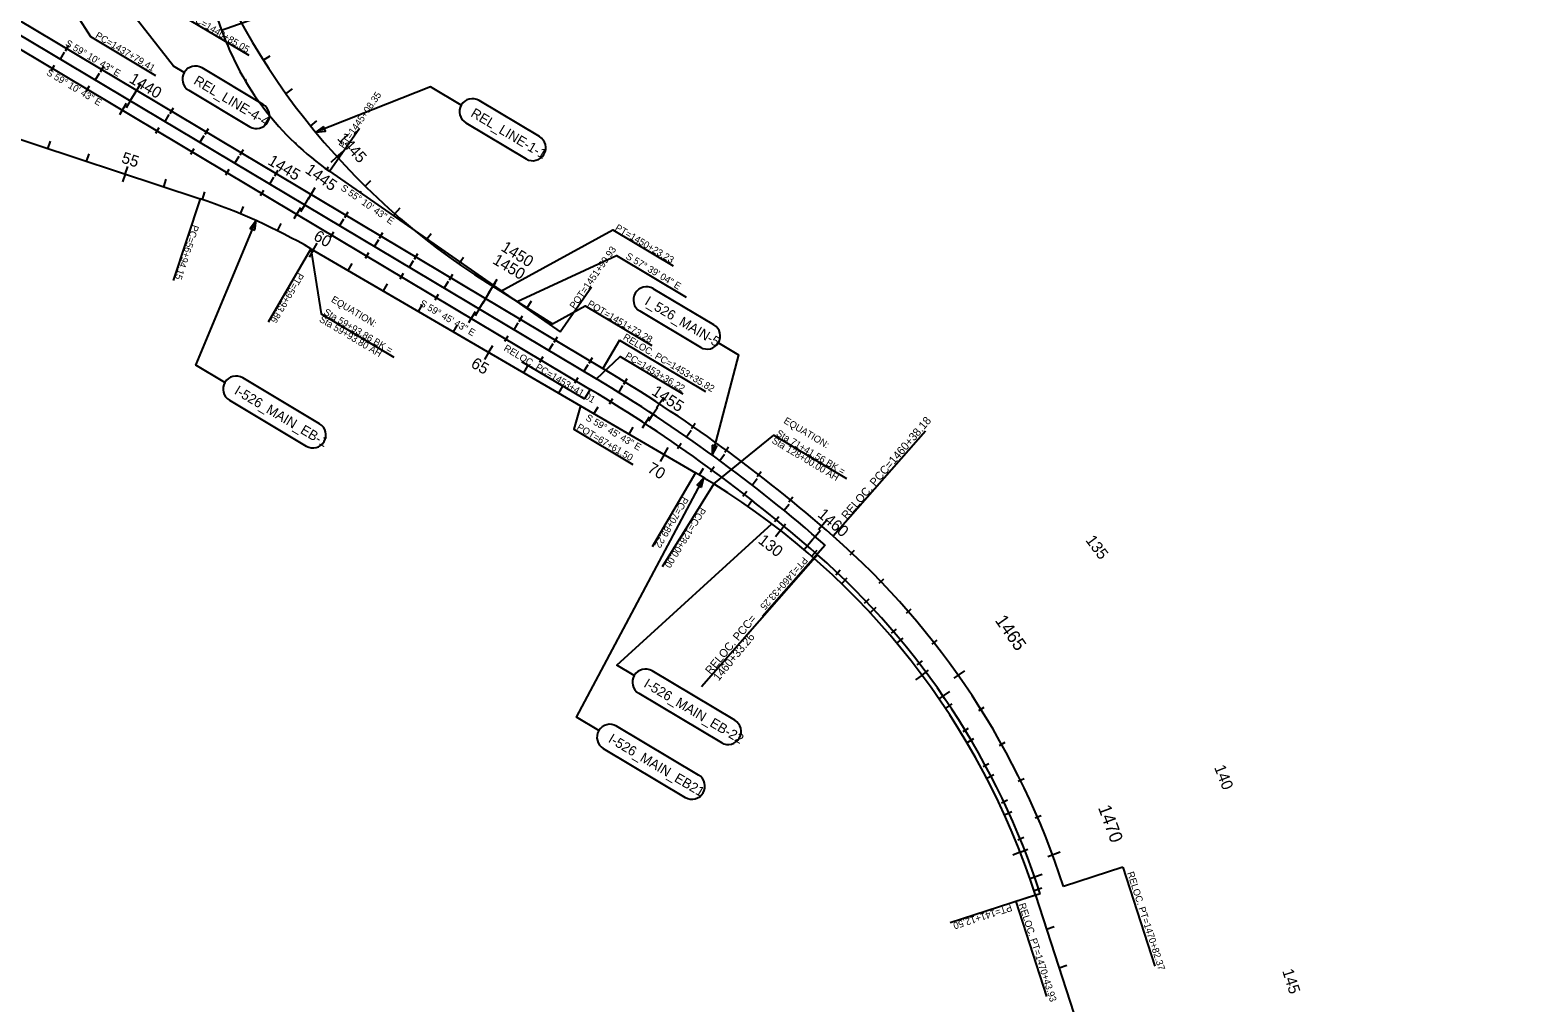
# Model space of a CAD drawing. Extents: x 2339300 to 2355400, y 360879 to 381052.
# Drawn here: x 2349719 to 2353429, y 365467 to 367862 of the extents above; entities that cross this region are included whole.
import ezdxf

# ---------------------------------------------------------------- set-up
doc = ezdxf.new("R2010")
doc.units = 0
for name, color, linetype in [('RD_HC_Cl', 7, 'Continuous'), ('RD_HC_CL_Rel', 7, 'Continuous'), ('RD_HC_Data', 7, 'Continuous'), ('RD_HC_Data_Rel', 7, 'Continuous'), ('RD_HC_Data_Tic', 7, 'Continuous'), ('RD_HC_Data_Tic_Rel', 7, 'Continuous'), ('RD_HC_TX_Rel_Sta50', 7, 'Continuous'), ('RD_HC_TX_Sta50', 7, 'Continuous')]:
    doc.layers.add(name, color=color, linetype=linetype)

msp = doc.modelspace()

# ---------------------------------------------------------------- linework, layer by layer
at = {"layer": 'RD_HC_Cl'}
for p, q in [((2346281.6, 369885.4), (2351112.4, 367003.2)), ((2350024.7, 368324.9), (2350189.7, 367861.9)), ((2348946.1, 367839.1), (2350136.8, 367446.4)), ((2350455.3, 367514.3), (2351023.1, 367119.4)), ((2350409.6, 367323.6), (2351072.9, 366937)), ((2351072.9, 366937), (2351356, 366771.9)), ((2352192.8, 365732.2), (2353428.7, 361905))]:
    msp.add_line(p, q, dxfattribs=at)
for centre, radius, start, end in [((2350864.3, 368102.3), 716.2, 199.6124, 235.1785), ((2349688.3, 366086.1), 1432.4, 59.7618, 71.7499), ((2349155.3, 363723), 3819.7, 48.7231, 59.1785), ((2350415.3, 365158.2), 1867.9, 58.1564, 59.7618), ((2350415.3, 365158.2), 1867.9, 17.896, 58.1564)]:
    msp.add_arc(centre, radius, start, end, dxfattribs=at)
at = {"layer": 'RD_HC_CL_Rel'}
for p, q in [((2348614.8, 368528.3), (2351127.8, 367029)), ((2348584, 368476.8), (2351097, 366977.5))]:
    msp.add_line(p, q, dxfattribs=at)
for centre, radius, start, end in [((2349155.3, 363723), 3849.7, 48.7252, 59.1785), ((2349155.3, 363723), 3789.7, 48.7126, 59.1785), ((2350414.7, 365157.8), 1940.6, 17.896, 48.7252), ((2350416, 365158.6), 1879.1, 17.896, 48.7126)]:
    msp.add_arc(centre, radius, start, end, dxfattribs=at)
at = {"layer": 'RD_HC_Data'}
for p, q in [((2350189.7, 367861.9), (2350312.2, 367905.5)), ((2350292, 367679.1), (2350141.6, 367768.8)), ((2350108.8, 367713.8), (2350259.2, 367624.1)), ((2350972, 367599.9), (2350823.5, 367688.5)), ((2350455.3, 367514.3), (2350529.3, 367620.6)), ((2350790.7, 367633.6), (2350939.2, 367544.9)), ((2350136.8, 367446.4), (2350070.7, 367245.7)), ((2350409.6, 367323.6), (2350304.2, 367142.7)), ((2351023.1, 367119.4), (2351099.9, 367229.8)), ((2351401.2, 367136.2), (2351251.5, 367225.4)), ((2351218.7, 367170.5), (2351368.4, 367081.2)), ((2350431, 366892.8), (2350241.8, 367005.7)), ((2350209, 366950.8), (2350398.2, 366837.9)), ((2351356, 366771.9), (2351249.7, 366589.5)), ((2351400.8, 366744.9), (2351273.9, 366540.5)), ((2351675.2, 366593.6), (2351521.1, 366418.1)), ((2351452.7, 366162.9), (2351249.1, 366284.3)), ((2351216.3, 366229.4), (2351419.9, 366107.9)), ((2351363.7, 366028), (2351161.8, 366148.5)), ((2351129, 366093.5), (2351330.9, 365973.1)), ((2352192.8, 365732.2), (2351982.4, 365664.2))]:
    msp.add_line(p, q, dxfattribs=at)
for points in [[(2350097.8, 367757.7), (2350071.6, 367773.3), (2349979.6, 367890.6)], [(2350779.6, 367677.5), (2350704, 367722.6), (2350421.3, 367610.5)], [(2350197.9, 366994.7), (2350126.7, 367037.1), (2350274.7, 367392.9)], [(2350409.6, 367323.6), (2350434.6, 367163.7), (2350613.8, 367056.8)], [(2351412.3, 367092.3), (2351461.9, 367062.7), (2351396.9, 366815.8)], [(2351112.4, 367003.2), (2351170.7, 367058.3), (2351324.7, 366966.4)], [(2351072.9, 366937), (2351056.7, 366879.3), (2351201.8, 366792.8)], [(2351400.8, 366744.9), (2351548.5, 366864.6), (2351727.1, 366758.1)], [(2351118, 366137.4), (2351062.8, 366170.3), (2351376.1, 366760)], [(2351205.2, 366273.3), (2351162.1, 366299), (2351544.1, 366646.6)]]:
    msp.add_lwpolyline(points, dxfattribs=at)
for points in [[(2350440.5, 367624.8), (2350421.3, 367610.5), (2350445.1, 367613.2)], [(2350271.5, 367369.1), (2350274.7, 367392.9), (2350260, 367373.9)], [(2351396.8, 366839.8), (2351396.9, 366815.8), (2351408.8, 366836.6)], [(2351370.7, 366736.6), (2351376.1, 366760), (2351359.7, 366742.5)]]:
    msp.add_lwpolyline(points, close=True, dxfattribs=at)
for centre, start, end in [((2350125.2, 367741.3), 59.1784, 239.1784), ((2350275.6, 367651.6), 239.1784, 59.1784), ((2350807.1, 367661.1), 59.1784, 239.1784), ((2350955.6, 367572.4), 239.1784, 59.1784), ((2351235.1, 367198), 59.1784, 239.1784), ((2351384.8, 367108.7), 239.1784, 59.1784), ((2350225.4, 366978.3), 59.1784, 239.1784), ((2350414.6, 366865.3), 239.1784, 59.1784), ((2351232.7, 366256.9), 59.1784, 239.1784), ((2351145.4, 366121), 59.1784, 239.1784), ((2351436.3, 366135.4), 239.1784, 59.1784), ((2351347.3, 366000.6), 239.1784, 59.1784)]:
    msp.add_arc(centre, 32, start, end, dxfattribs=at)
at = {"layer": 'RD_HC_Data_Rel'}
for p, q in [((2350877, 367219.4), (2351003.7, 367139.1)), ((2351169.3, 367098.6), (2351127.8, 367029)), ((2351169.3, 367098.6), (2351380.9, 366972.3)), ((2350927.9, 367046.4), (2351083, 366953.9)), ((2351097, 366977.5), (2351083, 366953.9)), ((2351921.5, 366874.4), (2351694.9, 366616.2)), ((2351655.9, 366570.6), (2351370.5, 366245.6)), ((2352407.6, 365801.3), (2352261.4, 365754.1)), ((2352407.6, 365801.3), (2352486.2, 365557.7)), ((2352204.2, 365736.1), (2352144.3, 365716.7)), ((2352144.3, 365716.7), (2352219.9, 365482.6))]:
    msp.add_line(p, q, dxfattribs=at)
for points in [[(2350072.1, 368005), (2350092.2, 367898.3), (2350256.6, 367800.3)], [(2349833.3, 367899.1), (2349867.6, 367845.8), (2350027.4, 367750.5)], [(2350877, 367219.4), (2351152.7, 367370.2), (2351301.1, 367281.6)], [(2350917.1, 367193.9), (2351161.6, 367307), (2351332.7, 367204.9)], [(2351003.7, 367139.1), (2351084.7, 367182.8), (2351248.1, 367085.3)]]:
    msp.add_lwpolyline(points, dxfattribs=at)
msp.add_arc((2351779.9, 368732.5), 1762, 199.588, 239.1733, dxfattribs=at)
at = {"layer": 'RD_HC_Data_Tic'}
for p, q in [((2349793.1, 367790.3), (2349803.4, 367807.5)), ((2350202.7, 367828), (2350206.4, 367829.6)), ((2349879, 367739.1), (2349889.3, 367756.3)), ((2350247.3, 367738.6), (2350250.7, 367740.7)), ((2349964.9, 367687.9), (2349975.1, 367705)), ((2349964.9, 367687.9), (2349954.6, 367670.7)), ((2350303.9, 367656.3), (2350307, 367658.8)), ((2350050.8, 367636.6), (2350061, 367653.8)), ((2349762.5, 367569.8), (2349768.8, 367588.8)), ((2350136.6, 367585.4), (2350146.9, 367602.6)), ((2350371.4, 367582.6), (2350374.2, 367585.5)), ((2349857.5, 367538.5), (2349863.7, 367557.5)), ((2350222.5, 367534.1), (2350232.8, 367551.3)), ((2349952.5, 367507.2), (2349958.7, 367526.2)), ((2350448.5, 367519.1), (2350453.2, 367525.6)), ((2349952.5, 367507.2), (2349946.2, 367488.2)), ((2350047.4, 367475.9), (2350053.7, 367494.9)), ((2350308.4, 367482.9), (2350318.6, 367500.1)), ((2350142.4, 367444.6), (2350148.7, 367463.5)), ((2350394.3, 367431.7), (2350404.5, 367448.8)), ((2350530.6, 367462), (2350532.9, 367465.2)), ((2350236, 367409.6), (2350243.7, 367428.1)), ((2350394.3, 367431.7), (2350384, 367414.5)), ((2350612.7, 367404.9), (2350615, 367408.1)), ((2350327, 367368.1), (2350336, 367386)), ((2350480.2, 367380.4), (2350490.4, 367397.6)), ((2350415, 367320.4), (2350425, 367337.7)), ((2350566, 367329.2), (2350576.3, 367346.4)), ((2350694.8, 367347.8), (2350697.1, 367351)), ((2350415, 367320.4), (2350404.9, 367303.2)), ((2350501.4, 367270.1), (2350511.4, 367287.4)), ((2350651.9, 367278), (2350662.2, 367295.1)), ((2350776.9, 367290.7), (2350779.1, 367293.9)), ((2350587.8, 367219.7), (2350597.8, 367237)), ((2350737.8, 367226.7), (2350748, 367243.9)), ((2350859, 367233.6), (2350863.5, 367240.1)), ((2350674.2, 367169.4), (2350684.2, 367186.6)), ((2350823.7, 367175.5), (2350813.4, 367158.3)), ((2350823.7, 367175.5), (2350833.9, 367192.7)), ((2350941, 367176.5), (2350943.3, 367179.7)), ((2350909.5, 367124.3), (2350919.8, 367141.4)), ((2350760.5, 367119), (2350770.6, 367136.3)), ((2350846.9, 367068.6), (2350836.9, 367051.4)), ((2350846.9, 367068.6), (2350857, 367085.9)), ((2350995.4, 367073), (2351005.7, 367090.2)), ((2350933.3, 367018.3), (2350943.4, 367035.6)), ((2351081.3, 367021.8), (2351091.5, 367039)), ((2351019.7, 366967.9), (2351029.8, 366985.2)), ((2351166.9, 366970.1), (2351177.4, 366987.1)), ((2351106.1, 366917.6), (2351116.2, 366934.8)), ((2351251.2, 366916.3), (2351240.2, 366899.6)), ((2351251.2, 366916.3), (2351262.2, 366933)), ((2351192.5, 366867.2), (2351202.6, 366884.5)), ((2351334.1, 366860.4), (2351345.5, 366876.8)), ((2351278.9, 366816.8), (2351268.8, 366799.6)), ((2351278.9, 366816.8), (2351289, 366834.1)), ((2351415.5, 366802.3), (2351427.3, 366818.4)), ((2351365.3, 366766.5), (2351375.5, 366783.7)), ((2351495.3, 366742), (2351507.5, 366757.8)), ((2351484.3, 366689.9), (2351495.8, 366706.3)), ((2351573.5, 366679.7), (2351586.2, 366695.2)), ((2351564.8, 366630.5), (2351552.5, 366614.8)), ((2351564.8, 366630.5), (2351577.1, 366646.3)), ((2351650.1, 366615.4), (2351663.2, 366630.6)), ((2351650.1, 366615.4), (2351637, 366600.3)), ((2351641.9, 366566.9), (2351655, 366582)), ((2351715.5, 366499.2), (2351729.4, 366513.6)), ((2351785.4, 366427.8), (2351800.1, 366441.3)), ((2351851.4, 366352.6), (2351866.8, 366365.4)), ((2351913.3, 366274.1), (2351929.3, 366286)), ((2351913.3, 366274.1), (2351897.2, 366262.1)), ((2351970.8, 366192.3), (2351987.5, 366203.4)), ((2352023.9, 366107.6), (2352041.2, 366117.8)), ((2352072.4, 366020.2), (2352090.2, 366029.4)), ((2352116.2, 365930.2), (2352134.4, 365938.5)), ((2352155.1, 365838.1), (2352173.7, 365845.4)), ((2352155.1, 365838.1), (2352136.4, 365830.8)), ((2352188.9, 365744.1), (2352207.9, 365750.3)), ((2352219.7, 365648.9), (2352238.8, 365655)), ((2352250.4, 365553.7), (2352269.5, 365559.9))]:
    msp.add_line(p, q, dxfattribs=at)
at = {"layer": 'RD_HC_Data_Tic_Rel'}
for p, q in [((2349805.8, 367810.7), (2349814, 367824.5)), ((2349770.6, 367761.9), (2349778.8, 367775.6)), ((2349891.7, 367759.5), (2349899.9, 367773.2)), ((2350292.2, 367788.2), (2350309.1, 367798.9)), ((2350292.2, 367788.2), (2350309.1, 367798.9)), ((2349856.5, 367710.6), (2349864.7, 367724.4)), ((2349974.5, 367703.1), (2349990.9, 367730.6)), ((2350348.2, 367705.4), (2350364.4, 367717)), ((2350348.2, 367705.4), (2350364.4, 367717)), ((2349939.3, 367654.2), (2349955.7, 367681.7)), ((2350063.4, 367657), (2350071.6, 367670.8)), ((2350028.2, 367608.2), (2350036.4, 367621.9)), ((2350408.8, 367625.8), (2350424.3, 367638.4)), ((2350408.8, 367625.8), (2350424.3, 367638.4)), ((2350149.3, 367605.8), (2350157.5, 367619.5)), ((2350114.1, 367556.9), (2350122.3, 367570.7)), ((2350235.2, 367554.5), (2350243.4, 367568.3)), ((2350473.7, 367549.8), (2350458.9, 367536.4)), ((2350473.7, 367549.8), (2350458.9, 367536.4)), ((2350473.7, 367549.8), (2350488.6, 367563.2)), ((2350473.7, 367549.8), (2350488.6, 367563.2)), ((2350200, 367505.7), (2350208.2, 367519.4)), ((2350321, 367503.3), (2350329.2, 367517.1)), ((2350403.9, 367446.9), (2350420.2, 367474.4)), ((2350542.9, 367477.6), (2350557, 367491.9)), ((2350542.9, 367477.6), (2350557, 367491.9)), ((2350285.8, 367454.4), (2350294, 367468.2)), ((2350368.6, 367398.1), (2350385, 367425.5)), ((2350492.8, 367400.8), (2350501, 367414.6)), ((2350616.1, 367409.5), (2350629.3, 367424.5)), ((2350616.1, 367409.5), (2350629.3, 367424.5)), ((2350457.6, 367352), (2350465.8, 367365.7)), ((2350578.7, 367349.6), (2350586.9, 367363.3)), ((2350693, 367345.6), (2350705.4, 367361.3)), ((2350693, 367345.6), (2350705.4, 367361.3)), ((2350543.5, 367300.7), (2350551.7, 367314.5)), ((2350664.6, 367298.4), (2350672.8, 367312.1)), ((2350773.4, 367286.2), (2350784.9, 367302.6)), ((2350773.4, 367286.2), (2350784.9, 367302.6)), ((2350629.4, 367249.5), (2350637.5, 367263.2)), ((2350750.4, 367247.1), (2350758.6, 367260.9)), ((2350833.2, 367190.7), (2350849.6, 367218.2)), ((2350857.1, 367231.4), (2350846.6, 367214.4)), ((2350857.1, 367231.4), (2350846.6, 367214.4)), ((2350857.1, 367231.4), (2350867.6, 367248.5)), ((2350857.1, 367231.4), (2350867.6, 367248.5)), ((2350715.2, 367198.3), (2350723.4, 367212)), ((2350941.8, 367178.3), (2350952.5, 367195.2)), ((2350941.8, 367178.3), (2350952.5, 367195.2)), ((2350798, 367141.9), (2350814.4, 367169.4)), ((2350922.2, 367144.7), (2350930.4, 367158.4)), ((2350887, 367095.8), (2350895.2, 367109.5)), ((2351008.1, 367093.4), (2351016.3, 367107.2)), ((2350972.9, 367044.6), (2350981.1, 367058.3)), ((2351093.9, 367042.2), (2351102.1, 367055.9)), ((2351058.7, 366993.3), (2351066.9, 367007.1)), ((2351179.5, 366990.5), (2351187.9, 367004.1)), ((2351144.3, 366941.7), (2351152.7, 366955.3)), ((2351260.3, 366931.8), (2351277.9, 366958.6)), ((2351225.2, 366883.1), (2351242.8, 366909.9)), ((2351346.4, 366881), (2351355.5, 366894.2)), ((2351311.3, 366832.3), (2351320.4, 366845.5)), ((2351427.7, 366823), (2351437.1, 366836)), ((2351392.6, 366774.4), (2351402.1, 366787.3)), ((2351507.4, 366763), (2351517.2, 366775.6)), ((2351472.3, 366714.3), (2351482.1, 366726.9)), ((2351585.6, 366700.9), (2351595.7, 366713.3)), ((2351550.4, 366652.1), (2351560.6, 366664.5)), ((2351658.2, 366632.2), (2351679.1, 366656.4)), ((2351623, 366583.3), (2351643.9, 366607.6)), ((2351736.6, 366570.3), (2351747.5, 366582)), ((2351701.1, 366521.3), (2351712.1, 366533)), ((2351807.6, 366500.4), (2351819.1, 366511.5)), ((2351771.8, 366451), (2351783.4, 366462.1)), ((2351874.9, 366426.9), (2351887, 366437.4)), ((2351838.6, 366377.1), (2351850.8, 366387.5)), ((2351938.3, 366350), (2351950.9, 366359.8)), ((2351901.4, 366299.7), (2351914.1, 366309.4)), ((2351992.8, 366266.5), (2352019, 366284.9)), ((2351955.1, 366215.7), (2351981.5, 366233.8)), ((2352052.9, 366186.9), (2352066.4, 366195.4)), ((2352014.2, 366135.4), (2352027.9, 366143.8)), ((2352103.7, 366101.1), (2352117.7, 366109)), ((2352063.9, 366049), (2352078, 366056.6)), ((2352150.1, 366012.9), (2352164.4, 366020)), ((2352109, 365960.1), (2352123.4, 365967)), ((2352191.8, 365922.4), (2352206.5, 365928.7)), ((2352149.2, 365868.9), (2352164, 365875)), ((2352223.2, 365827.7), (2352253.2, 365838.9)), ((2352178.9, 365773.7), (2352209.1, 365784.3))]:
    msp.add_line(p, q, dxfattribs=at)

# ---------------------------------------------------------------- texts
at = {"layer": 'RD_HC_Data'}
for s, height, rotation, p in [('REL_LINE-4-4', 24, 329.1784, (2350119.1, 367731)), ('PT=1445+08.35', 17, 55.1785, (2350490.8, 367568.8)), ('REL_LINE-1-1', 24, 329.1784, (2350800.9, 367650.8)), ('S 55%%d 10\' 43" E', 17, 325.1785, (2350481.4, 367469.6)), ('PC=56+94.15', 17, 251.7499, (2350118.4, 367384)), ('POT=1451+99.93', 17, 55.1785, (2351058.6, 367173.9)), ('PT=59+93.86', 17, 239.7618, (2350378.6, 367266.4)), ('Sta 59+93.86 BK = ', 17, 329.1784, (2350439.4, 367163.3)), ('EQUATION:', 17, 329.1784, (2350457.8, 367194.2)), ('S 59%%d 45\' 43" E', 17, 329.7618, (2350675.7, 367184.7)), ('I_526_MAIN-5', 24, 329.1784, (2351229, 367187.7)), ('Sta 59+93.80 AH', 17, 329.1784, (2350428.6, 367145.3)), ('PC=1453+36.22', 17, 329.1784, (2351181.2, 367055.7)), ('I-526_MAIN_EB-1', 24, 329.1784, (2350219.2, 366967.9)), ('S 59%%d 45\' 43" E', 17, 329.7618, (2351084.1, 366903)), ('POT=67+61.50', 17, 329.1784, (2351062.3, 366880)), ('EQUATION:', 17, 329.1784, (2351571.4, 366895.7)), ('Sta 128+00.00 AH', 17, 329.1784, (2351542.2, 366846.8)), ('Sta 71+41.56 BK = ', 17, 329.1784, (2351553, 366864.8)), ('PC=70+89.22', 17, 239.7618, (2351325, 366714.7)), ('PCC=128+00.00', 17, 238.1564, (2351368.2, 366688.7)), ('PT=1460+33.25', 17, 228.7231, (2351621.2, 366566.5)), ('I-526_MAIN_EB-22', 24, 329.1784, (2351226.6, 366246.6)), ('I-526_MAIN_EB21', 24, 329.1784, (2351139.3, 366110.7)), ('PT=141+12.50', 17, 197.896, (2352131.6, 365710.3))]:
    msp.add_text(s, height=height, rotation=rotation, dxfattribs=at).set_placement(p)
at = {"layer": 'RD_HC_Data_Rel'}
for s, height, rotation, p in [('PCC=1440+85.05', 17, 329.1784, (2350095.9, 367898.3)), ('PC=1437+79.41', 17, 329.1785, (2349877.5, 367844)), ('S 59%%d 10\' 43" E', 17, 329.1785, (2349803.7, 367824.8)), ('S 59%%d 10\' 43" E', 17, 329.1785, (2349757, 367752.9)), ('PT=1450+23.23', 17, 329.1784, (2351156.5, 367370.7)), ('S 57%%d 39\' 04" E', 17, 329.1784, (2351182.7, 367300.6)), ('POT=1451+73.28', 17, 329.1784, (2351088.5, 367183.5)), ('RELOC. PC=1453+35.82', 17, 329.1785, (2351176, 367101.5)), ('RELOC. PC=1453+41.01', 17, 329.1785, (2350882.5, 367074.4)), ('RELOC. PCC=1460+38.18', 20, 49.359, (2351728.2, 366656.1)), ('RELOC. PCC=', 20, 50.4568, (2351393.2, 366274.3)), ('1460+33.26', 20, 50.4568, (2351412.7, 366258.1)), ('RELOC. PT=1470+82.37', 17, 287.896, (2352417.8, 365787.3)), ('RELOC. PT=1470+43.93', 17, 287.896, (2352151, 365709.9))]:
    msp.add_text(s, height=height, rotation=rotation, dxfattribs=at).set_placement(p)
at = {"layer": 'RD_HC_TX_Rel_Sta50'}
for s, height, rotation, p in [('1445', 28, 312.1593, (2350472.9, 367594.1)), ('1450', 28, 328.418, (2350875.2, 367320.6)), ('1465', 32, 305.0901, (2352091.5, 366408.7)), ('1470', 32, 290.3278, (2352346, 365947.9))]:
    msp.add_text(s, height=height, rotation=rotation, dxfattribs=at).set_placement(p)
at = {"layer": 'RD_HC_TX_Sta50'}
for s, rotation, p in [('1440', 329.1785, (2349960.1, 367734.7)), ('55', 341.7499, (2349941.4, 367536.4)), ('1445', 329.1785, (2350301.3, 367533)), ('1445', 324.5106, (2350393.2, 367512.6)), ('60', 329.7618, (2350413.8, 367347.1)), ('1450', 329.1785, (2350854.5, 367288.9)), ('65', 329.7618, (2350801.1, 367033.9)), ('1455', 326.7219, (2351245.9, 366966.2)), ('70', 329.7618, (2351235.3, 366775.7)), ('1460', 319.2219, (2351654.5, 366666.3)), ('130', 322.0215, (2351507.9, 366601.4)), ('135', 306.6842, (2352314.4, 366606)), ('140', 291.3469, (2352631.7, 366047.1)), ('145', 287.896, (2352799.3, 365546.2))]:
    msp.add_text(s, height=28, rotation=rotation, dxfattribs=at).set_placement(p)

doc.saveas('drawing.dxf')
